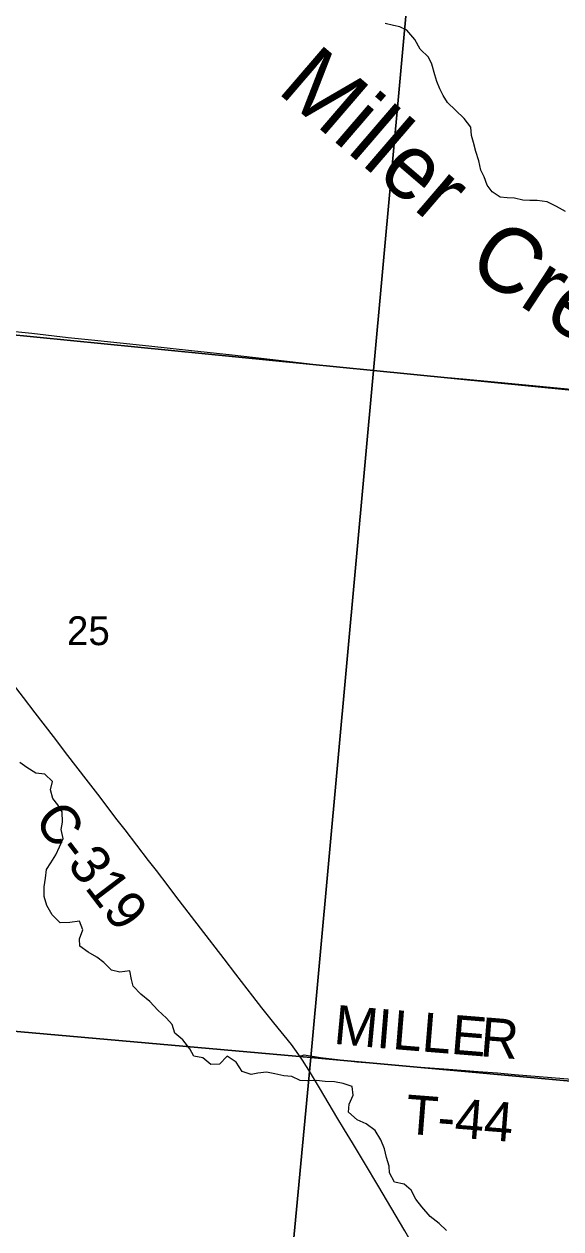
# Model space of a CAD drawing. Extents: x 1410790 to 1770854, y 566777 to 831614.
# Drawn here: x 1576223 to 1580335, y 714986 to 724224 of the extents above; entities that cross this region are included whole.
import ezdxf

# ---------------------------------------------------------------- set-up
doc = ezdxf.new("R2010")
doc.units = 0
for name, color, linetype in [('GM_X_County_Road', 7, 'Continuous'), ('GM_X_County_Road_Text', 7, 'Continuous'), ('GM_X_Minor_River', 7, 'Continuous'), ('GM_X_Minor_River_Text', 7, 'Continuous'), ('GM_X_Section', 7, 'Continuous'), ('GM_X_Section_Text', 7, 'Continuous'), ('GM_X_Township_Road', 7, 'Continuous'), ('GM_X_Township_Road_Text', 7, 'Continuous')]:
    doc.layers.add(name, color=color, linetype=linetype)

msp = doc.modelspace()

# ---------------------------------------------------------------- linework, layer by layer
at = {"layer": 'GM_X_County_Road'}
for points in [[(1578333.9, 716312.2), (1578310.5, 716346.4), (1578270.9, 716398.8), (1578137.3, 716564.8), (1578045.4, 716680.2), (1577975.2, 716770.8), (1577845.4, 716940), (1577755.4, 717056.9), (1577575.4, 717290.6), (1577505.2, 717381.3), (1577385.4, 717537.2), (1577325.9, 717615.6), (1577236.4, 717732.8), (1577176.7, 717811), (1576997, 718045.2), (1576937.2, 718123.4), (1576787.2, 718318), (1576697.4, 718435.1), (1576557.1, 718616.8), (1576447.5, 718760.1), (1576307.7, 718942), (1576218.4, 719059.4), (1576108.4, 719202.4), (1576098.3, 719215.6)], [(1580017.1, 713499.7), (1579954.8, 713604.5), (1579879.1, 713731.2), (1579801.5, 713860.8), (1579727.2, 713984.1), (1579676.3, 714068.3), (1579499.3, 714363.7), (1579440.7, 714462.4), (1579323.6, 714659.7), (1579273.3, 714744.1), (1579181.7, 714899.4), (1579140.2, 714970.2), (1579064.6, 715096.8), (1578939.8, 715308.8), (1578831.3, 715492.4), (1578737.5, 715646.4), (1578678.6, 715744.8), (1578619.6, 715843.3), (1578494.3, 716054.8), (1578417.9, 716181.2), (1578356.6, 716278.4), (1578333.9, 716312.2)]]:
    msp.add_lwpolyline(points, dxfattribs=at)
at = {"layer": 'GM_X_Minor_River'}
for points in [[(1580370.4, 722787.7), (1580302.7, 722824.6), (1580231, 722861.5), (1580152.9, 722872.4), (1580096.7, 722871.1), (1580044.6, 722873.7), (1579980.6, 722888.5), (1579924.5, 722891.1), (1579870.4, 722897.8), (1579808.7, 722938.6), (1579771.2, 722989.1), (1579748, 723053.5), (1579722.5, 723104), (1579707.3, 723174.3), (1579684.1, 723246.7), (1579664.9, 723315.1), (1579651.5, 723369.4), (1579644.3, 723433.6), (1579595, 723500.4), (1579527.6, 723563.3), (1579466.1, 723622.2), (1579432.7, 723676.7), (1579407.2, 723727.1), (1579385.9, 723783.5), (1579368.5, 723835.8), (1579345.4, 723916.2), (1579320, 723970.7), (1579256.5, 724031.5), (1579215.3, 724106.2), (1579154, 724177.1), (1579102.2, 724203.7), (1579052.2, 724214.3), (1578988.2, 724229.1)], [(1577718.8, 716248.9), (1577652.6, 716245.6), (1577591, 716296.5), (1577523, 716311.3), (1577493.6, 716365.8), (1577438.3, 716434.6), (1577376.8, 716485.4), (1577357.5, 716551.8), (1577314, 716602.5), (1577248.6, 716663.4), (1577187.2, 716728.3), (1577117.7, 716785.2), (1577058.3, 716848.1), (1577046.9, 716898.3), (1577033.7, 716964.7), (1576957.4, 716955.5), (1576893.4, 716970.3), (1576833.9, 717029.2), (1576780.3, 717069.9), (1576712.6, 717108.8), (1576648.9, 717153.6), (1576647.6, 717209.8), (1576672.5, 717279.7), (1576647.3, 717344.1), (1576573, 717334.9), (1576498.7, 717331.8), (1576439.3, 717392.7), (1576396.1, 717465.3), (1576376.9, 717535.7), (1576377.8, 717607.9), (1576386.6, 717674), (1576393.4, 717742), (1576428.2, 717793.8), (1576467, 717853.5), (1576493.9, 717915.3), (1576522.7, 717979.1), (1576507.5, 718047.5), (1576516.3, 718105.5), (1576515.2, 718183.7), (1576481.8, 718236.2), (1576442.3, 718286.8), (1576425, 718353.2), (1576439.9, 718417.2), (1576382.4, 718472), (1576312.3, 718480.8), (1576244.6, 718523.7), (1576191, 718562.4)], [(1579459.9, 714973.2), (1579402.5, 715028), (1579332.9, 715081), (1579269.7, 715153.9), (1579224.3, 715212.6), (1579189, 715283.2), (1579133.4, 715330), (1579061.4, 715344.9), (1579022.2, 715415.5), (1579020.8, 715465.7), (1578999.6, 715534.1), (1578984.4, 715600.4), (1578955.1, 715669), (1578911.9, 715739.7), (1578842.3, 715790.6), (1578774.5, 715821.5), (1578707, 715880.4), (1578713.8, 715942.5), (1578744.7, 716010.3), (1578735.5, 716076.6), (1578667.7, 716101.4), (1578599.6, 716112.3), (1578529.4, 716115.1), (1578463.4, 716123.9), (1578391.1, 716120.7), (1578339, 716123.3), (1578273.2, 716154.2), (1578213.1, 716158.9), (1578143.1, 716175.7), (1578081.1, 716186.5), (1578014.8, 716179.2), (1577962.5, 716169.8), (1577892.6, 716192.7), (1577847.3, 716263.4), (1577777.7, 716310.3), (1577718.8, 716248.9)]]:
    msp.add_lwpolyline(points, dxfattribs=at)
at = {"layer": 'GM_X_Section'}
for points in [[(1574037, 727327.4), (1579377.5, 726810.9), (1578900.5, 721567.6), (1573737.9, 722079.3)], [(1579377.5, 726810.9), (1584812, 726253.6), (1584282.6, 721032.4), (1578900.5, 721567.6)], [(1573737.9, 722079.3), (1578900.5, 721567.6), (1578419.1, 716300.4), (1573281.6, 716755.8)], [(1578900.5, 721567.6), (1584282.6, 721032.4), (1583863.1, 715803.7), (1578419.1, 716300.4)], [(1573281.6, 716755.8), (1578419.1, 716300.4), (1577923.7, 711041.4), (1572586.3, 711496.1)], [(1578419.1, 716300.4), (1583863.1, 715803.7), (1583457.2, 710550.8), (1577923.7, 711041.4)]]:
    msp.add_lwpolyline(points, close=True, dxfattribs=at)
at = {"layer": 'GM_X_Township_Road'}
for points in [[(1573955.6, 722083.5), (1574003.5, 722076.7), (1574207.6, 722056), (1574746.8, 722004.1), (1575335, 721948.5), (1575531, 721929.1), (1575710.7, 721911.6), (1575922.9, 721889.9), (1576282.1, 721852.9), (1576559.4, 721821.8), (1576738.9, 721802.6), (1577179.8, 721757.4), (1577506, 721720.4), (1577816.1, 721687.2), (1577995.5, 721667.1), (1578435.9, 721617.4), (1578664.5, 721593.7), (1579236, 721535.2), (1579611.9, 721500.2), (1579906, 721472.5), (1580494.2, 721417.3), (1580804.3, 721390), (1581577.1, 721318.1)], [(1578333.9, 716312.2), (1578352.4, 716315.9), (1578369.7, 716319.3), (1578384.5, 716318.4), (1578494.3, 716300.1), (1578624.4, 716284), (1578771, 716267.8), (1578901.4, 716255.7), (1579048.3, 716243.3), (1579195.1, 716231.5), (1579260.4, 716226.3), (1579472.9, 716210.6), (1579701.7, 716193), (1579848.8, 716181.4), (1579979.9, 716170.9), (1580453.2, 716130.7), (1580632.6, 716116.6), (1580836.7, 716102.3), (1581054.6, 716090.2), (1581112.3, 716086.3)]]:
    msp.add_lwpolyline(points, dxfattribs=at)

# ---------------------------------------------------------------- texts
at = {"layer": 'GM_X_County_Road_Text'}
msp.add_text('C-319', height=300, rotation=307.3054, dxfattribs=at).set_placement((1576289.8, 718116.7))
at = {"layer": 'GM_X_Minor_River_Text'}
for s, height, rotation, p in [('Miller', 499.92, 319.34707, (1578151.9, 723706.8)), ('Creek', 499.94, 326.74049, (1579598.7, 722340.9))]:
    msp.add_text(s, height=height, rotation=rotation, dxfattribs=at).set_placement(p)
at = {"layer": 'GM_X_Section_Text'}
msp.add_text('25', height=221, rotation=0.00001, dxfattribs=at).set_placement((1576551, 719461.8))
at = {"layer": 'GM_X_Township_Road_Text'}
for s, rotation, p in [('M', 354.67, (1578588.2, 716405.9)), ('I', 355.36856, (1578916.3, 716375.3)), ('L', 355.35345, (1579039.1, 716365.4)), ('L', 355.35345, (1579262.8, 716347.2)), ('E', 355.35345, (1579486.4, 716329)), ('R', 355.35645, (1579710.1, 716310.8)), ('T-44', 355.52214, (1579137.1, 715717.2))]:
    msp.add_text(s, height=300, rotation=rotation, dxfattribs=at).set_placement(p)

doc.saveas('drawing.dxf')
